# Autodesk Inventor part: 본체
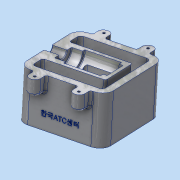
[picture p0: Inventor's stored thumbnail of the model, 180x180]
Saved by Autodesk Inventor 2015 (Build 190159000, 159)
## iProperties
Created: 2018-01
Part Number: 본체
Material: 알루미늄 6061
Document SubType Name: Modeling
Designer: SCD-A011
Density: 2.7 g/cm^3
Appearance: 알루미늄 - 평지
Mass: 996.83 g
Surface Area: 836.721 cm^2
Volume: 369.196 cm^3
Author: SCD-A011
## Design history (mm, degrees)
sketch "스케치3"
  geometry: L1 (0, 0)-(110, 0); L2 (110, 0)-(110, 65); L3 (110, 65)-(0, 65); L4 (0, 65)-(0, 0); L5 (0, 65)-(19, 65); L6 (19, 65)-(19, 57.5); L7 (19, 57.5)-(0, 57.5); L8 (0, 57.5)-(0, 65); L9 (19, 65)-(33, 65); L10 (33, 65)-(33, 49); L11 (33, 49)-(19, 49); L12 (19, 49)-(19, 65); L13 (33, 65)-(80, 65); L14 (80, 65)-(80, 45); L15 (80, 45)-(33, 45); L16 (33, 45)-(33, 65); L17 (80, 65)-(85, 65); L18 (85, 65)-(85, 50); L19 (85, 50)-(80, 50); L20 (80, 50)-(80, 65); L21 (0, 65)-(110, 65); L22 (110, 65)-(110, 0); L23 (110, 0)-(0, 0); L24 (0, 0)-(0, 65)
  constraints: 48 end point, 12 parallel, 6 horizontal, 6 perpendicular
  dimensions: "d4" = 110 distance of L2.end L3.end; "d5" = 65 distance of L1.end L2.end; "d6" = 19 distance of L6.end L7.end; "d7" = 7.5 distance of L5.end L6.end; "d8" = 14 distance of L10.end L11.end; "d9" = 16 distance of L9.end L10.end; "d10" = 47 distance of L14.end L15.end; "d11" = 20 distance of L13.end L14.end; "d12" = 5 distance of L18.end L19.end; "d13" = 15 distance of L17.end L18.end
extrude "돌출1" new body sketch "스케치3" stored distance "d14" = 110; taper "d15" = 0 deg
revolve "회전1" stored, may be unused: angle "d16" = 90 deg
sketch "스케치4"
  geometry: L1 (0, 0)-(0, -45); L2 (0, 0)-(45, 0); L3 (0, -45)-(-100, -45); L4 (-100, -45)-(-100, 45); L5 (-100, 45)-(-10, 45); L6 (-10, 45)-(-10, 25); L7 (-10, 25)-(-90, 25); L8 (-90, 25)-(-90, -25); L9 (-90, -25)-(0, -25); L10 (0, -25)-(-10, -25); L11 (-10, -25)-(-10, -45)
  constraints: 22 end point, 7 perpendicular, 2 point on line, 1 horizontal, 1 parallel
  dimensions: "d18" = 90 deg angle of L1 L2 (derived); "d19" = 100 distance of L1.end L3.end; "d20" = 90 distance of L3.end L4.end; "d21" = 90 deg angle of L3 L4 (derived); "d22" = 90 distance of L4.end L5.end; "d23" = 90 deg angle of L4 L5 (derived); "d24" = 20 distance of L5.end L6.end; "d25" = 90 deg angle of L5 L6 (derived); "d26" = 80 distance of L6.end L7.end; "d27" = 90 deg angle of L6 L7 (derived); "d28" = 50 distance of L7.end L8.end; "d29" = 90 deg angle of L8 L7 (derived); "d30" = 90 distance of L8.end L9.end; "d31" = 90 deg angle of L9 L8 (derived); "d32" = 10 distance of L9.end L10.end
extrude "돌출2" cut sketch "스케치4" distance "d33" = 65; taper "d34" = 0 deg
sketch "스케치5"
  geometry: L1 (90, 0)-(90, 65) reference; L2 (90, 65)-(90, 30); L3 (90, 65)-(125, 65); L4 (90, 30)-(10, 8.564); L5 (10, 0)-(10, 65) reference; L6 (100, 0)-(100, 65) reference; L7 (100, 65)-(90, 65); L8 (10, 65)-(100, 65) reference; L9 (100, 0)-(10, 0); L10 (100, 0)-(100, 65) reference; 1 further point
  constraints: 10 end point, 2 collinear, 2 perpendicular, 1 horizontal, 1 point on line
  dimensions: "d35" = 35 distance of L1.end L2.end; "d36" = 90 deg angle of L2 L3 (derived); "d38" = 105 deg angle of L2 L4
extrude "돌출3" cut sketch "스케치5" stored distance "d39" = 50; taper "d40" = 0 deg
sketch "스케치7"
  geometry: L1 (10, 65)-(100, 65) reference; L2 (0, 65)-(55, 65); L3 (80, 45)-(33, 45) reference; L4 (56.5, 45)-(75, 45); L5 (10, 8.564)-(90, 30) reference; L6 (0, 11.061)-(75, 31.157); L7 (75, 45)-(75, 31.157); L8 (56.5, 45)-(38, 45); L9 (56.5, 45)-(75, 45); L10 (38, 45)-(38, 39.243); L11 (0, 11.061)-(0, 29.061); L12 (0, 65)-(0, 0) reference; L13 (0, 29.061)-(38, 39.243); L14 (38, 45)-(75, 45); L15 (75, 45)-(75, 55); L16 (75, 55)-(38, 55); L17 (38, 55)-(38, 45); L18 (33, 65)-(33, 45) reference; L19 (80, 65)-(80, 45) reference; L20 (0, 0)-(110, 0) reference
  constraints: 26 end point, 3 horizontal, 2 collinear, 2 parallel, 2 perpendicular, 2 point on line, 1 vertical
  dimensions: "d61" = 18.5 distance of L4.start L4.end; "d62" = 5 distance between parallel lines of L6 L5; "d63" = 18.5 distance of L4.start L8.end; "d64" = 180 deg angle of L8 L9 (derived); "d65" = 18 distance of L6.start L11.end; "d66" = 105 deg angle of L11 L13; "d67" = 37 distance of L16.end L15.end; "d108" = 5 distance between parallel lines of L17 L18; "d109" = 5 distance between parallel lines of L19 L15 (derived); "d110" = 31.15714 distance from line of L20 L6.end
extrude "돌출4" cut sketch "스케치7" stored distance "d69" = 30; taper "d70" = 0 deg
sketch "스케치8"
  geometry: L1 (110, 0)-(0, 0) reference; L2 (110, 110)-(110, 0) reference; L3 (34.5, 120)-(34.5, 110); L4 (19.5, 120)-(19.5, 110); L5 (19.5, 110)-(34.5, 110); L6 (0, 55)-(110, 55); L7 (0, 110)-(110, 110) reference; L8 (55, 110)-(55, 0); L9 (90.5, 110)-(75.5, 110); L10 (75.5, 120)-(75.5, 110); L11 (90.5, 120)-(90.5, 110); L12 (19.5, 0)-(34.5, 0); L13 (19.5, -10)-(19.5, 0); L14 (34.5, -10)-(34.5, 0); L15 (75.5, -10)-(75.5, 0); L16 (90.5, 0)-(75.5, 0); L17 (90.5, -10)-(90.5, 0); A1 r 7.5 centre (27, 120) between (34.5, 120) and (19.5, 120); A2 r 7.5 centre (83, 120) between (90.5, 120) and (75.5, 120); A3 r 7.5 centre (27, -10) between (19.5, -10) and (34.5, -10); A4 r 7.5 centre (83, -10) between (75.5, -10) and (90.5, -10)
  constraints: 28 end point, 15 symmetric about line, 8 point on circle, 4 centre point, 3 midpoint, 2 tangent, 1 horizontal, 3 other
extrude "돌출5" join sketch "스케치8" distance "d75" = 20; taper "d76" = 0 deg
fillet "모깎기1" dims "d77" = 1
fillet "모깎기2" dims "d78" = 5
fillet "모깎기3" dims "d79" = 3
fillet "모깎기4" dims "d80" = 15
fillet "모깎기6" dims "d82" = 3
fillet "모깎기7" dims "d83" = 3
chamfer "모따기1" distance "d84" = 1; stored, may be unused: second distance "d85" = 2, angle "d86" = 45 deg
sketch "스케치9"
  geometry: A1 r 7.5 centre (0, 0) between (-7.5, 0) and (7.5, 0) reference; A2 r 7.5 centre (56, 0) between (48.5, 0) and (63.5, 0) reference; A3 r 7.5 centre (56, 130) between (63.5, 130) and (48.5, 130) reference; A4 r 7.5 centre (0, 130) between (7.5, 130) and (-7.5, 130) reference; 5 further points
  constraints: 4 coincident
hole "구멍1" sketch "스케치9" at (0, 130), (56, 130), (56, 0), (0, 0) diameter "d87" = 3.459; stored, may be unused: countersink angle "d91" = 90 deg, drill point angle "d93" = 118 deg; dims "d88" = 9, "d89" = 4, "d90" = 2, "d92" = 11
sketch "스케치10"
  geometry: 2 further points
  constraints: 1 other
  dimensions: "d95" = 55 horizontal distance of point (55, 20) point (0, 0); "d96" = 20 vertical distance of point (0, 0) point (55, 20)
feature "엠보싱1" sketch "스케치10" dims "d4" = 110, "d5" = 65, "d6" = 19, "d7" = 7.5, "d8" = 14, "d9" = 16, "d10" = 47, "d11" = 20, "d12" = 5, "d13" = 15, "d97" = 0.5, "d98" = 0
chamfer "모따기2" distance "d99" = 1; stored, may be unused: second distance "d100" = 2, angle "d101" = 45 deg
fillet "모깎기10" dims "d103" = 3
fillet "모깎기11" dims "d104" = 3
fillet "모깎기12" dims "d105" = 3
fillet "모깎기13" dims "d106" = 3
fillet "모깎기14" dims "d107" = 3
node "솔리드1"
